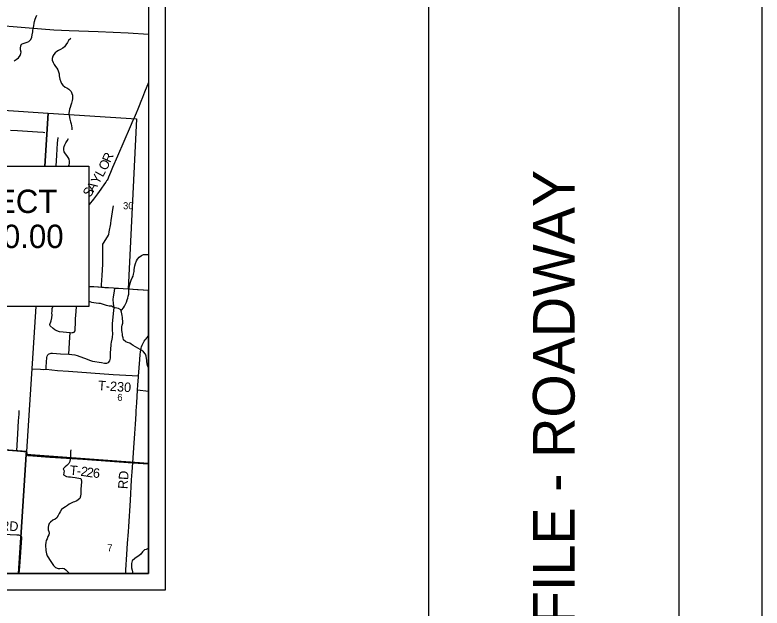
# Model space of a CAD drawing. Extents: x 0 to 34, y 0 to 26.1.
# Drawn here: x 29.516 to 34, y 13.893 to 17.45 of the extents above; entities that cross this region are included whole.
import ezdxf

# ---------------------------------------------------------------- set-up
doc = ezdxf.new("R2010")
doc.units = 0
for name, color, linetype in [('GM_X_County_Road', 7, 'Continuous'), ('GM_X_County_Road_Text', 7, 'Continuous'), ('GM_X_Minor_River', 7, 'Continuous'), ('GM_X_Section', 7, 'Continuous'), ('GM_X_Section_Text', 7, 'Continuous'), ('GM_X_State_Route', 7, 'Continuous'), ('GM_X_Township_Road', 7, 'Continuous'), ('GM_X_Township_Road_Text', 7, 'Continuous'), ('SH_Border', 7, 'Continuous'), ('SH_Cut_Line', 7, 'Continuous'), ('SH_Data', 7, 'Continuous'), ('SH_Text', 7, 'Continuous')]:
    doc.layers.add(name, color=color, linetype=linetype)

msp = doc.modelspace()

# ---------------------------------------------------------------- linework, layer by layer
at = {"layer": 'GM_X_County_Road'}
for points in [[(29.9598, 15.8225), (29.9641, 15.8222), (30.0129, 15.819), (30.0345, 15.8176), (30.0561, 15.8163), (30.1072, 15.813), (30.1163, 15.8124), (30.1384, 15.8109), (30.2523, 15.8032), (30.3167, 15.7988)], [(30.2236, 14.7649), (30.2293, 14.8533), (30.2349, 14.9401), (30.2387, 14.9962), (30.2429, 15.0581), (30.2441, 15.0767), (30.2466, 15.1232), (30.2517, 15.1995), (30.2538, 15.2317), (30.2573, 15.2772), (30.2578, 15.2832), (30.2651, 15.3835), (30.2679, 15.4144), (30.2698, 15.4299), (30.2719, 15.4422), (30.274, 15.4521), (30.2763, 15.4604), (30.2795, 15.4696), (30.2831, 15.478), (30.2875, 15.4863), (30.2924, 15.4946), (30.2977, 15.5021), (30.3027, 15.5086), (30.3074, 15.514), (30.3118, 15.5185), (30.3164, 15.5229), (30.3167, 15.5231)], [(30.1809, 14.1), (30.1823, 14.1219), (30.1877, 14.2149), (30.1923, 14.2831), (30.1968, 14.3513), (30.199, 14.3823), (30.2088, 14.5373), (30.2164, 14.6614), (30.2203, 14.7109), (30.2236, 14.7649)]]:
    msp.add_lwpolyline(points, dxfattribs=at)
at = {"layer": 'GM_X_Minor_River'}
for points in [[(29.5779, 17.284), (29.5893, 17.2876), (29.5999, 17.2917), (29.6106, 17.3022), (29.6172, 17.317), (29.6197, 17.3314), (29.6225, 17.3488), (29.6238, 17.3594), (29.6266, 17.3742), (29.6286, 17.3859), (29.6314, 17.4003), (29.6342, 17.4121), (29.637, 17.4253), (29.6412, 17.4355), (29.6471, 17.4495)], [(29.5119, 17.1757), (29.523, 17.1832), (29.5364, 17.1933), (29.5479, 17.2065), (29.5522, 17.2182), (29.5523, 17.228), (29.5497, 17.2406), (29.5491, 17.2512), (29.5508, 17.2645), (29.5562, 17.2743), (29.5657, 17.2795), (29.5779, 17.284)], [(29.8505, 17.3085), (29.8383, 17.2968), (29.8309, 17.2859), (29.8217, 17.2708), (29.8132, 17.2587), (29.8037, 17.2512), (29.7903, 17.2427), (29.7781, 17.2363), (29.7678, 17.2315), (29.7575, 17.224), (29.7498, 17.2135), (29.7429, 17.2025), (29.739, 17.19), (29.7385, 17.1794), (29.7444, 17.1657), (29.7522, 17.1538), (29.7601, 17.142), (29.7668, 17.1317), (29.7727, 17.121), (29.7771, 17.1096), (29.7804, 17.0966), (29.7818, 17.086), (29.7832, 17.0757), (29.785, 17.0654), (29.7905, 17.0498), (29.7961, 17.0388), (29.8032, 17.0292), (29.817, 17.0169), (29.8269, 17.0126), (29.8396, 17.0045), (29.8524, 16.9907), (29.8579, 16.98), (29.8609, 16.969), (29.8619, 16.9587), (29.861, 16.9466), (29.8594, 16.9364), (29.8554, 16.9212), (29.8515, 16.9095), (29.8468, 16.8963), (29.8429, 16.8849), (29.8409, 16.8717), (29.84, 16.8614), (29.841, 16.8485), (29.8424, 16.8348), (29.8449, 16.8245), (29.8485, 16.8097), (29.8533, 16.7967), (29.8558, 16.7846), (29.8576, 16.7732), (29.8571, 16.7622)], [(29.8374, 16.5425), (29.8404, 16.5498), (29.8436, 16.5623), (29.8437, 16.5729), (29.8412, 16.5858), (29.836, 16.5961), (29.8282, 16.6072), (29.8192, 16.6183), (29.8117, 16.6294), (29.8088, 16.6408), (29.8089, 16.6515), (29.8109, 16.6617), (29.8148, 16.6715), (29.821, 16.6844), (29.8284, 16.696), (29.8368, 16.71)], [(30.1508, 15.682), (30.1584, 15.6819), (30.1672, 15.6936), (30.1741, 15.7045), (30.1796, 15.7151), (30.185, 15.7279), (30.1897, 15.7408), (30.1925, 15.7514), (30.196, 15.7642), (30.1988, 15.7748), (30.1996, 15.7854), (30.2001, 15.7961), (30.201, 15.8093), (30.2019, 15.8192), (30.2047, 15.8336), (30.209, 15.8487), (30.2137, 15.8593), (30.2195, 15.8733), (30.2246, 15.8846), (30.2281, 15.8967), (30.2309, 15.9119), (30.2322, 15.9225), (30.2335, 15.9361), (30.2355, 15.9464), (30.2394, 15.9604), (30.2453, 15.9747), (30.2514, 15.9864), (30.2622, 15.9977), (30.2748, 16.0078), (30.2873, 16.013), (30.2998, 16.014), (30.3093, 16.0143), (30.3167, 16.0134)], [(29.9895, 15.7246), (29.9778, 15.7267), (29.9668, 15.7294), (29.9598, 15.7322)], [(30.3167, 15.3338), (30.312, 15.3463), (30.3087, 15.36), (30.3073, 15.3695), (30.3066, 15.3794), (30.3056, 15.39), (30.3035, 15.4033), (30.3002, 15.4151), (30.2875, 15.4293), (30.2777, 15.4377), (30.2668, 15.4447), (30.2533, 15.4528), (30.2389, 15.459), (30.2246, 15.4687), (30.2145, 15.4764), (30.2047, 15.4814), (30.1915, 15.4857), (30.1809, 15.4904), (30.1682, 15.5019), (30.166, 15.5137), (30.1624, 15.5259), (30.1606, 15.5365), (30.1588, 15.5479), (30.1578, 15.5574), (30.1575, 15.5684), (30.1584, 15.5805), (30.16, 15.5908), (30.1628, 15.6021), (30.163, 15.615), (30.1623, 15.6249), (30.1605, 15.6363), (30.1591, 15.6481), (30.1574, 15.6576), (30.1563, 15.6675), (30.1508, 15.682), (30.1376, 15.6904), (30.1278, 15.6909), (30.1165, 15.6948), (30.1055, 15.6988), (30.0946, 15.703), (30.0813, 15.7047), (30.0658, 15.7075), (30.053, 15.7126), (30.0413, 15.7161), (30.03, 15.7193), (30.0186, 15.7205), (30.0027, 15.7226), (29.9895, 15.7246)], [(29.8504, 14.8422), (29.8503, 14.8319), (29.8498, 14.8202), (29.8493, 14.8103), (29.8484, 14.7948), (29.8468, 14.7853), (29.8448, 14.7728), (29.8386, 14.7599), (29.8267, 14.7491), (29.8168, 14.7408), (29.806, 14.7284), (29.8108, 14.7155), (29.8099, 14.7052), (29.8083, 14.6923), (29.8245, 14.6827), (29.8373, 14.681), (29.8494, 14.6794), (29.8619, 14.6773), (29.8774, 14.6753), (29.888, 14.6748), (29.899, 14.6728), (29.9115, 14.6696), (29.9162, 14.657), (29.9154, 14.6468), (29.9137, 14.6316), (29.9128, 14.6222), (29.9124, 14.6119), (29.9121, 14.5873), (29.9116, 14.5774), (29.9103, 14.5641), (29.9056, 14.5509), (29.8865, 14.5367), (29.874, 14.5311), (29.8645, 14.5278), (29.8542, 14.5226), (29.842, 14.5159), (29.8309, 14.5092), (29.8195, 14.5009), (29.8088, 14.4942), (29.7954, 14.4849), (29.787, 14.4713), (29.7815, 14.4603), (29.7753, 14.4483), (29.768, 14.4347), (29.7577, 14.4264), (29.7436, 14.4197), (29.7298, 14.4093), (29.7214, 14.3995), (29.7164, 14.3885), (29.7144, 14.3779), (29.7157, 14.3631), (29.7194, 14.3517), (29.7204, 14.3422), (29.7188, 14.332), (29.7141, 14.3214), (29.7087, 14.3093), (29.704, 14.2976), (29.7005, 14.2862), (29.6984, 14.273), (29.7002, 14.2593), (29.7012, 14.2494), (29.7015, 14.2392), (29.7033, 14.2289), (29.7054, 14.2194), (29.7099, 14.2064), (29.7169, 14.1942), (29.7236, 14.1843), (29.7315, 14.1724), (29.7397, 14.1606), (29.7482, 14.148), (29.7599, 14.1357), (29.7753, 14.1295), (29.7852, 14.1297), (29.7985, 14.1334), (29.8117, 14.1302), (29.8215, 14.1233), (29.8327, 14.1114), (29.8433, 14.1)], [(30.3167, 14.2517), (30.3165, 14.2513), (30.3035, 14.2446), (30.2936, 14.2432), (30.2818, 14.2304), (30.2714, 14.2161), (30.2588, 14.2072), (30.2489, 14.2008), (30.2347, 14.19), (30.2194, 14.1768), (30.2147, 14.1609), (30.2146, 14.1477), (30.2159, 14.1336), (30.2188, 14.1203), (30.2206, 14.1108), (30.2235, 14.1)]]:
    msp.add_lwpolyline(points, dxfattribs=at)
at = {"layer": 'GM_X_Section'}
for points in [[(29.1833, 16.5425), (29.2063, 16.8961), (29.7144, 16.8614), (29.6947, 16.5425)], [(29.6947, 16.5425), (29.7144, 16.8614), (30.2458, 16.8283), (30.1945, 15.8061), (29.9598, 15.8216)], [(29.6421, 15.7025), (29.5845, 14.8326), (29.5829, 14.814), (30.3167, 14.7611), (30.3167, 15.7987), (30.1945, 15.8061), (29.9598, 15.8216)], [(29.6421, 15.7025), (29.5845, 14.8326), (28.5788, 14.9085), (28.6244, 15.7025)]]:
    msp.add_lwpolyline(points, dxfattribs=at)
for points in [[(28.5264, 14.1), (29.5379, 14.1), (29.5829, 14.814), (29.5845, 14.8326), (28.5788, 14.9085)], [(29.5379, 14.1), (30.3167, 14.1), (30.3167, 14.7611), (29.5829, 14.814)]]:
    msp.add_lwpolyline(points, close=True, dxfattribs=at)
at = {"layer": 'GM_X_State_Route'}
msp.add_lwpolyline([(29.2512, 17.4005), (29.3571, 17.3924), (29.6018, 17.3736), (29.7502, 17.3618), (29.841, 17.3569), (30.0155, 17.3502), (30.1955, 17.3437), (30.3167, 17.3357)], dxfattribs=at)
at = {"layer": 'GM_X_Township_Road'}
for p, q in [((30.3167, 15.1918), (30.2517, 15.1995)), ((30.2236, 14.7649), (30.3167, 14.7587))]:
    msp.add_line(p, q, dxfattribs=at)
for points in [[(30.3167, 17.0458), (30.307, 17.0203), (30.2945, 16.9869), (30.2825, 16.9562), (30.2723, 16.9306), (30.261, 16.9051), (30.2526, 16.8851), (30.2431, 16.8621), (30.2307, 16.8337), (30.2232, 16.8167), (30.2072, 16.7796), (30.1692, 16.6913), (30.1315, 16.6028), (30.1019, 16.5345), (30.0897, 16.5059), (30.0781, 16.4778), (30.0751, 16.4707), (30.0727, 16.4654), (30.0696, 16.4598), (30.0662, 16.4547), (30.0614, 16.448), (30.0544, 16.4376), (30.031, 16.4052), (30.012, 16.3783), (29.9866, 16.3447), (29.9615, 16.3134), (29.9598, 16.3111)], [(29.4902, 16.7599), (29.5306, 16.7571), (29.6517, 16.7491), (29.6859, 16.7471), (29.6952, 16.7463)], [(29.7638, 16.5425), (29.7678, 16.61), (29.7721, 16.6823), (29.7744, 16.7148)], [(30.0345, 15.8176), (30.0359, 15.8317), (30.0391, 15.8886), (30.0433, 15.9564), (30.0425, 16.0305), (30.0427, 16.041), (30.0431, 16.0707), (30.0432, 16.075), (30.0513, 16.0883), (30.0772, 16.1306), (30.0792, 16.134), (30.0822, 16.1495), (30.0913, 16.1983), (30.0921, 16.2024), (30.0944, 16.2179), (30.1061, 16.2963), (30.1076, 16.3062)], [(30.0968, 15.4954), (30.1009, 15.5153), (30.1031, 15.5402), (30.1009, 15.5592), (30.1017, 15.5982), (30.1085, 15.6807), (30.1112, 15.6945), (30.1079, 15.7203), (30.105, 15.7433), (30.1065, 15.7606), (30.1144, 15.7947), (30.1163, 15.8124)], [(29.8392, 15.4155), (29.8429, 15.4834), (29.845, 15.5177), (29.8468, 15.5446), (29.7839, 15.5507), (29.7664, 15.5562), (29.7551, 15.5627), (29.7457, 15.5693), (29.7266, 15.5868), (29.7261, 15.5947), (29.7324, 15.6151), (29.7371, 15.6329), (29.7387, 15.6523), (29.7378, 15.6613), (29.7388, 15.674), (29.7394, 15.6894), (29.743, 15.7008), (29.7439, 15.7025)], [(29.8468, 15.5446), (29.8599, 15.5449), (29.8656, 15.5454), (29.8709, 15.5473), (29.8764, 15.5564), (29.8772, 15.5672), (29.879, 15.601), (29.8801, 15.6282), (29.8838, 15.6712), (29.8861, 15.7024), (29.8861, 15.7025)], [(29.7037, 15.3231), (29.7037, 15.3395), (29.7067, 15.3965), (29.7094, 15.4046), (29.7136, 15.4112), (29.7172, 15.4153), (29.7213, 15.4181), (29.7279, 15.4204), (29.7327, 15.4213), (29.7423, 15.4213), (29.7897, 15.4179), (29.8392, 15.4155), (29.8746, 15.4116), (29.8895, 15.4079), (29.9502, 15.3854), (29.9644, 15.3796), (29.9817, 15.3747), (30.0353, 15.366), (30.053, 15.362), (30.067, 15.3618), (30.0765, 15.3664), (30.0858, 15.3757), (30.0893, 15.3912), (30.0902, 15.4218), (30.0938, 15.4723), (30.096, 15.4914), (30.0968, 15.4954)], [(30.2578, 15.2832), (30.1053, 15.2928), (29.8383, 15.3115), (29.7723, 15.3156), (29.7037, 15.3231), (29.6881, 15.3221), (29.67, 15.3233), (29.6204, 15.3262)], [(29.5263, 14.8362), (29.5335, 14.9383), (29.5381, 15.0163), (29.5415, 15.0569), (29.5417, 15.0775)], [(29.0847, 14.8704), (29.1096, 14.868), (29.1775, 14.8637), (29.2964, 14.8537), (29.3433, 14.8498), (29.4214, 14.8437), (29.5263, 14.8362), (29.5703, 14.833), (29.5829, 14.8315), (29.585, 14.8304), (29.5866, 14.8251), (29.5872, 14.8147), (29.594, 14.809), (29.5968, 14.809), (29.5978, 14.8089)], [(29.1775, 14.8637), (29.2196, 14.5184), (29.2229, 14.5101), (29.2305, 14.4971), (29.2718, 14.4328), (29.2781, 14.418), (29.2874, 14.392), (29.2991, 14.3593), (29.3028, 14.3511), (29.3067, 14.3463), (29.3113, 14.3442), (29.3247, 14.3431), (29.5276, 14.332), (29.5368, 14.3317), (29.5434, 14.331), (29.5487, 14.3287), (29.5518, 14.3259)], [(29.5978, 14.8089), (29.725, 14.799), (29.9241, 14.7855), (30.2236, 14.7649)], [(29.5518, 14.3259), (29.5526, 14.3252), (29.555, 14.3207), (29.5544, 14.314), (29.5429, 14.1416), (29.54, 14.1)]]:
    msp.add_lwpolyline(points, dxfattribs=at)
at = {"layer": 'SH_Border'}
msp.add_line((32, 0.5), (32, 21.5), dxfattribs=at)
msp.add_lwpolyline([(1.5, 21.5), (33.5, 21.5), (33.5, 0.5), (1.5, 0.5)], close=True, dxfattribs=at)
at = {"layer": 'SH_Cut_Line'}
msp.add_lwpolyline([(0, 0), (34, 0), (34, 22), (0, 22)], close=True, dxfattribs=at)
at = {"layer": 'SH_Data'}
for points in [[(23.4167, 21), (30.4167, 21), (30.4167, 14), (23.4167, 14)], [(23.5167, 20.9), (30.3167, 20.9), (30.3167, 14.1), (23.5167, 14.1)], [(28.3097, 16.5425), (29.9598, 16.5425), (29.9598, 15.7025), (28.3097, 15.7025)]]:
    msp.add_lwpolyline(points, close=True, dxfattribs=at)

# ---------------------------------------------------------------- texts
at = {"layer": 'GM_X_County_Road_Text'}
msp.add_text('RD', height=0.05682, rotation=86.0545, dxfattribs=at).set_placement((30.191, 14.6055))
at = {"layer": 'GM_X_Section_Text'}
for s, height, p in [('30', 0.04186, (30.165, 16.2853)), ('6', 0.0419, (30.1304, 15.1361)), ('7', 0.0419, (30.0704, 14.2341))]:
    msp.add_text(s, height=height, rotation=0, dxfattribs=at).set_placement(p)
at = {"layer": 'GM_X_Township_Road_Text'}
for s, height, rotation, p in [('R', 0.0568, 65.8019, (30.0882, 16.5603)), ('O', 0.0568, 63.1676, (30.0644, 16.5131)), ('L', 0.0568, 61.3555, (30.0431, 16.4741)), ('Y', 0.0568, 60.3824, (30.0179, 16.4297)), ('S', 0.0568, 54.0177, (29.9639, 16.3513)), ('A', 0.0568, 56.3143, (29.9878, 16.3844)), ('T-230', 0.05682, 356.0747, (30.0132, 15.2011)), ('T', 0.0568, 355.315, (29.843, 14.6927)), ('-', 0.0568, 354.2218, (29.885, 14.6893)), ('2', 0.0568, 351.9965, (29.9077, 14.687)), ('2', 0.0568, 350.8174, (29.942, 14.6822)), ('6', 0.0568, 355.9215, (29.9821, 14.676)), ('RD', 0.05682, 357.0388, (29.4261, 14.36))]:
    msp.add_text(s, height=height, rotation=rotation, dxfattribs=at).set_placement(p)
at = {"layer": 'SH_Data'}
msp.add_text('GEOTECHNICAL PROFILE - ROADWAY', height=0.25, rotation=90, dxfattribs=at).set_placement((32.875, 10.3357))
at = {"layer": 'SH_Text'}
for s, p in [('END PROJECT', (28.4497, 16.2625)), ('STA. 568+00.00', (28.4497, 16.0525))]:
    msp.add_text(s, height=0.14, dxfattribs=at).set_placement(p)

doc.saveas('drawing.dxf')
